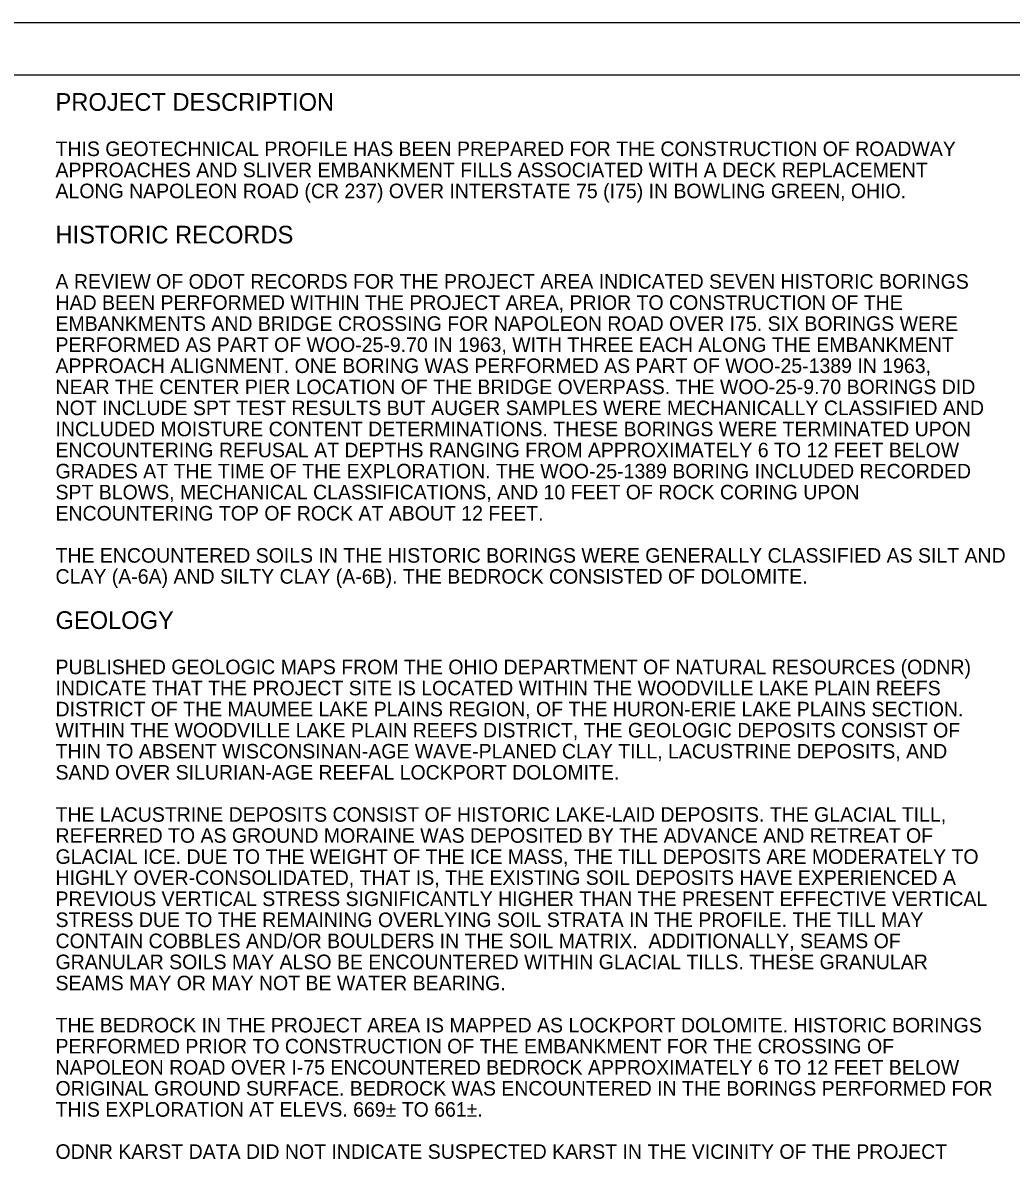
# Model space of a CAD drawing. Extents: x -59 to 43, y 0 to 22.
# Drawn here: x 2.1 to 11.6, y 11.05 to 22 of the extents above; entities that cross this region are included whole.
import ezdxf

# ---------------------------------------------------------------- set-up
doc = ezdxf.new("R2010")
doc.units = 0
for name, color, linetype in [('SH_Border', 7, 'Continuous'), ('SH_Cut_Line', 7, 'Continuous'), ('SH_Text', 7, 'Continuous')]:
    doc.layers.add(name, color=color, linetype=linetype)

msp = doc.modelspace()

# ---------------------------------------------------------------- linework, layer by layer
at = {"layer": 'SH_Border'}
msp.add_lwpolyline([(1.5, 21.5), (33.5, 21.5), (33.5, 0.5), (1.5, 0.5)], close=True, dxfattribs=at)
at = {"layer": 'SH_Cut_Line'}
msp.add_lwpolyline([(0, 0), (34, 0), (34, 22), (0, 22)], close=True, dxfattribs=at)

# ---------------------------------------------------------------- texts
at = {"layer": 'SH_Text'}
for s, height, p in [('PROJECT DESCRIPTION', 0.17, (2.417, 21.154)), ('THIS GEOTECHNICAL PROFILE HAS BEEN PREPARED FOR THE CONSTRUCTION OF ROADWAY ', 0.14, (2.417, 20.719)), ('APPROACHES AND SLIVER EMBANKMENT FILLS ASSOCIATED WITH A DECK REPLACEMENT ', 0.14, (2.417, 20.516)), ('ALONG NAPOLEON ROAD (CR 237) OVER INTERSTATE 75 (I75) IN BOWLING GREEN, OHIO.', 0.14, (2.417, 20.314)), ('HISTORIC RECORDS', 0.17, (2.417, 19.879)), ('A REVIEW OF ODOT RECORDS FOR THE PROJECT AREA INDICATED SEVEN HISTORIC BORINGS ', 0.14, (2.417, 19.444)), ('HAD BEEN PERFORMED WITHIN THE PROJECT AREA, PRIOR TO CONSTRUCTION OF THE ', 0.14, (2.417, 19.241)), ('EMBANKMENTS AND BRIDGE CROSSING FOR NAPOLEON ROAD OVER I75. SIX BORINGS WERE ', 0.14, (2.417, 19.039)), ('PERFORMED AS PART OF WOO-25-9.70 IN 1963, WITH THREE EACH ALONG THE EMBANKMENT ', 0.14, (2.417, 18.836)), ('APPROACH ALIGNMENT. ONE BORING WAS PERFORMED AS PART OF WOO-25-1389 IN 1963, ', 0.14, (2.417, 18.634)), ('NEAR THE CENTER PIER LOCATION OF THE BRIDGE OVERPASS. THE WOO-25-9.70 BORINGS DID ', 0.14, (2.417, 18.431)), ('NOT INCLUDE SPT TEST RESULTS BUT AUGER SAMPLES WERE MECHANICALLY CLASSIFIED AND ', 0.14, (2.417, 18.229)), ('INCLUDED MOISTURE CONTENT DETERMINATIONS. THESE BORINGS WERE TERMINATED UPON ', 0.14, (2.417, 18.026)), ('ENCOUNTERING REFUSAL AT DEPTHS RANGING FROM APPROXIMATELY 6 TO 12 FEET BELOW ', 0.14, (2.417, 17.824)), ('GRADES AT THE TIME OF THE EXPLORATION. THE WOO-25-1389 BORING INCLUDED RECORDED ', 0.14, (2.417, 17.621)), ('SPT BLOWS, MECHANICAL CLASSIFICATIONS, AND 10 FEET OF ROCK CORING UPON ', 0.14, (2.417, 17.419)), ('ENCOUNTERING TOP OF ROCK AT ABOUT 12 FEET.', 0.14, (2.417, 17.216)), ('THE ENCOUNTERED SOILS IN THE HISTORIC BORINGS WERE GENERALLY CLASSIFIED AS SILT AND ', 0.14, (2.417, 16.811)), ('CLAY (A-6A) AND SILTY CLAY (A-6B). THE BEDROCK CONSISTED OF DOLOMITE.', 0.14, (2.417, 16.609)), ('GEOLOGY', 0.17, (2.417, 16.174)), ('PUBLISHED GEOLOGIC MAPS FROM THE OHIO DEPARTMENT OF NATURAL RESOURCES (ODNR) ', 0.14, (2.417, 15.739)), ('INDICATE THAT THE PROJECT SITE IS LOCATED WITHIN THE WOODVILLE LAKE PLAIN REEFS ', 0.14, (2.417, 15.536)), ('DISTRICT OF THE MAUMEE LAKE PLAINS REGION, OF THE HURON-ERIE LAKE PLAINS SECTION. ', 0.14, (2.417, 15.334)), ('WITHIN THE WOODVILLE LAKE PLAIN REEFS DISTRICT, THE GEOLOGIC DEPOSITS CONSIST OF ', 0.14, (2.417, 15.131)), ('THIN TO ABSENT WISCONSINAN-AGE WAVE-PLANED CLAY TILL, LACUSTRINE DEPOSITS, AND ', 0.14, (2.417, 14.929)), ('SAND OVER SILURIAN-AGE REEFAL LOCKPORT DOLOMITE. ', 0.14, (2.417, 14.726)), ('THE LACUSTRINE DEPOSITS CONSIST OF HISTORIC LAKE-LAID DEPOSITS. THE GLACIAL TILL, ', 0.14, (2.417, 14.321)), ('REFERRED TO AS GROUND MORAINE WAS DEPOSITED BY THE ADVANCE AND RETREAT OF ', 0.14, (2.417, 14.119)), ('GLACIAL ICE. DUE TO THE WEIGHT OF THE ICE MASS, THE TILL DEPOSITS ARE MODERATELY TO ', 0.14, (2.417, 13.916)), ('HIGHLY OVER-CONSOLIDATED, THAT IS, THE EXISTING SOIL DEPOSITS HAVE EXPERIENCED A ', 0.14, (2.417, 13.714)), ('PREVIOUS VERTICAL STRESS SIGNIFICANTLY HIGHER THAN THE PRESENT EFFECTIVE VERTICAL ', 0.14, (2.417, 13.511)), ('STRESS DUE TO THE REMAINING OVERLYING SOIL STRATA IN THE PROFILE. THE TILL MAY ', 0.14, (2.417, 13.309)), ('CONTAIN COBBLES AND/OR BOULDERS IN THE SOIL MATRIX.  ADDITIONALLY, SEAMS OF ', 0.14, (2.417, 13.106)), ('GRANULAR SOILS MAY ALSO BE ENCOUNTERED WITHIN GLACIAL TILLS. THESE GRANULAR ', 0.14, (2.417, 12.904)), ('SEAMS MAY OR MAY NOT BE WATER BEARING.', 0.14, (2.417, 12.701)), ('THE BEDROCK IN THE PROJECT AREA IS MAPPED AS LOCKPORT DOLOMITE. HISTORIC BORINGS ', 0.14, (2.417, 12.296)), ('PERFORMED PRIOR TO CONSTRUCTION OF THE EMBANKMENT FOR THE CROSSING OF ', 0.14, (2.417, 12.094)), ('NAPOLEON ROAD OVER I-75 ENCOUNTERED BEDROCK APPROXIMATELY 6 TO 12 FEET BELOW ', 0.14, (2.417, 11.891)), ('ORIGINAL GROUND SURFACE. BEDROCK WAS ENCOUNTERED IN THE BORINGS PERFORMED FOR ', 0.14, (2.417, 11.689)), ('THIS EXPLORATION AT ELEVS. 669± TO 661±.', 0.14, (2.417, 11.486)), ('ODNR KARST DATA DID NOT INDICATE SUSPECTED KARST IN THE VICINITY OF THE PROJECT ', 0.14, (2.417, 11.081))]:
    msp.add_text(s, height=height, dxfattribs=at).set_placement(p)

doc.saveas('drawing.dxf')
